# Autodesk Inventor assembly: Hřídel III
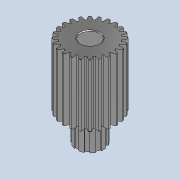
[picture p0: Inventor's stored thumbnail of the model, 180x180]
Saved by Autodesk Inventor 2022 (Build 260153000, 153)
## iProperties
Created: 2025-05
Part Number: Hřídel III
Document SubType Name: Assembly
Designer: jbart
Mass: 2650.81 g
Surface Area: 2605.11 cm^2
Volume: 2650.81 cm^3
Density: 1 g/cm^3
Author: jbart
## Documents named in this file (2)
- C:\Users\jbart\OneDrive\Dokumenty\Inventor\Převodovka navijáku\Hřídel III.iam
- C:\Users\jbart\OneDrive\Dokumenty\Inventor\Převodovka navijáku\Hřídel III\Design Accelerator\Čelní ozubená kola1.iam
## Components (1 placed, 1 different names)
1. Čelní ozubená kola:1 [sub-assembly]
